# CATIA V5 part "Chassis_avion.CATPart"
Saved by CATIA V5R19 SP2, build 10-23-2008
Part number: Chassis_avion
Bounding box of the stored display mesh (mm): x -50 to 50, y -1500 to 1500, z -900 to 900
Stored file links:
  C:\Users\matthieu\Desktop\IAO\modele_CAO\Chassis_avion.CATPart
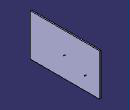
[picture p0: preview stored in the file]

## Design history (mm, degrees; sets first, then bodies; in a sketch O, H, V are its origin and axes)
Parameters
  h = 300 mm
  i = 900 mm
  hauteur_soute = 1800 mm
  largeur_soute = 3000 mm
Body1 (main body)
  Sketch1 on yz-plane, origin (0, 0, 0), H (0, 1, 0), V (0, 0, 1)
    circle A1 centre (0, 0) radius 15
    point P1 (0, 15)
    circle A2 centre (900, -300) radius 15
    point P2 (900, -300)
    line L1 (-1500, 900) -> (1500, 900)
    line L2 (1500, 900) -> (1500, -900)
    line L3 (1500, -900) -> (-1500, -900)
    line L4 (-1500, -900) -> (-1500, 900)
    radius A1 = 15
    radius A2 = 15
    distance P2 V = 900 {= i}
    distance H P2 = 300 {= h}
    distance L3 H = 900
    distance L1 H = 900
    distance L2 V = 1500
    distance V L4 = 1500
    coincidence: A1 P1, P1 V
    horizontal: L1 H, L3 H
    vertical: L2 V, L4 V
  MultiPad1: profile Sketch1, domains (length 0 / length 50; length 50 / length 50; length 50 / length 50)
Relations
  Value = largeur_soute /2
  Value = hauteur_soute /2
